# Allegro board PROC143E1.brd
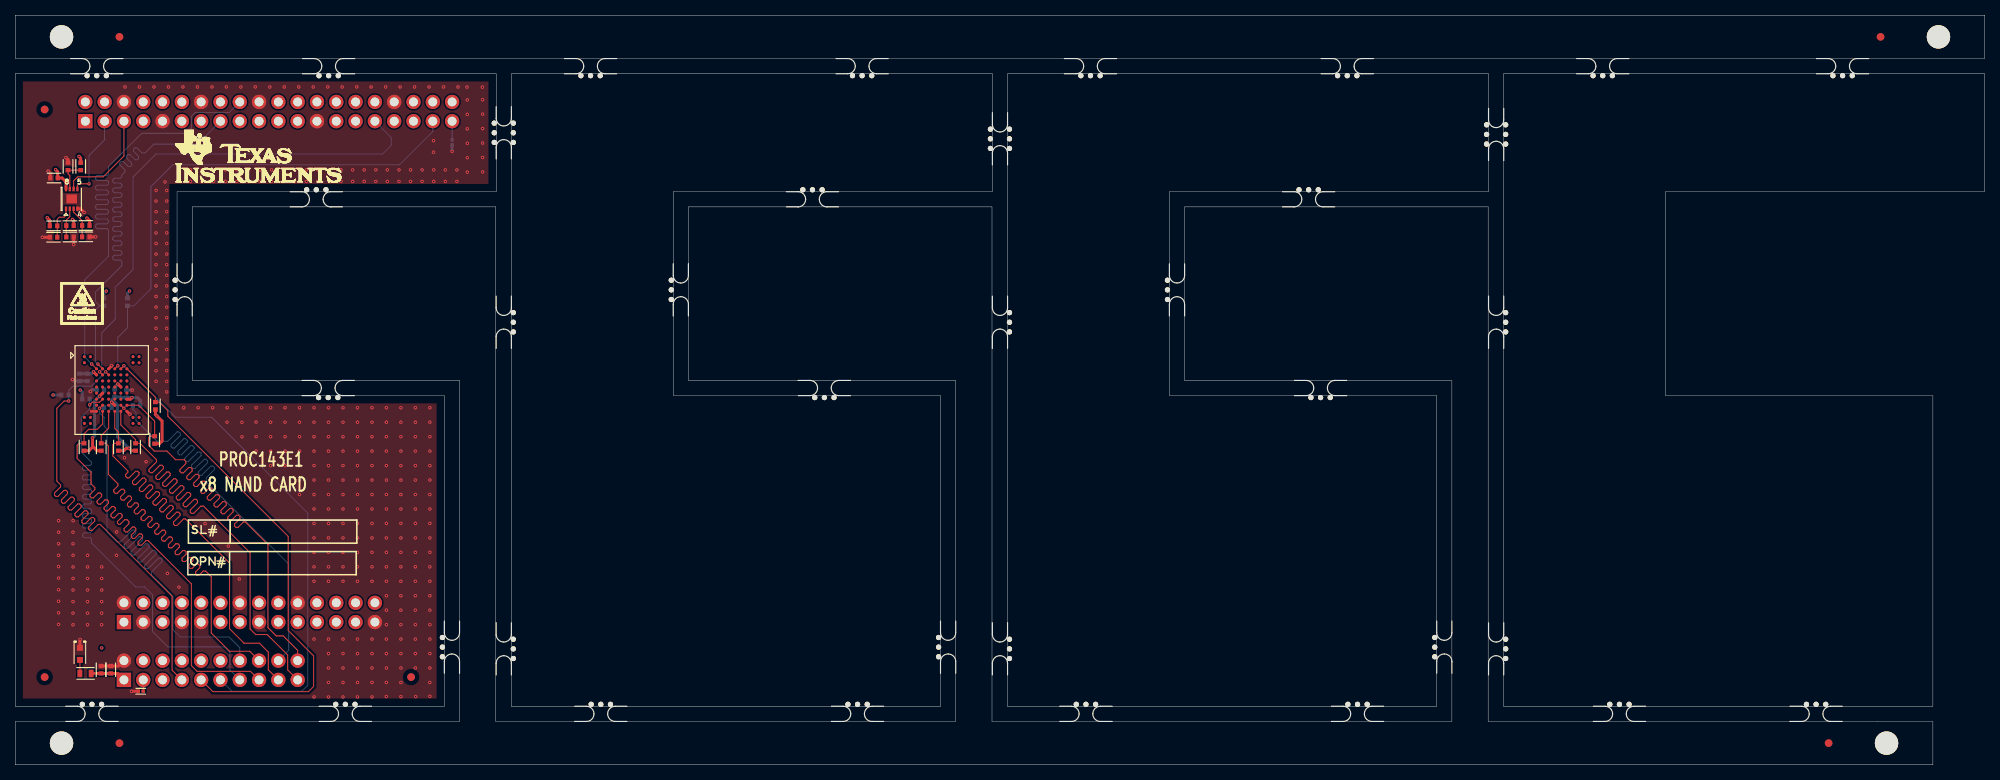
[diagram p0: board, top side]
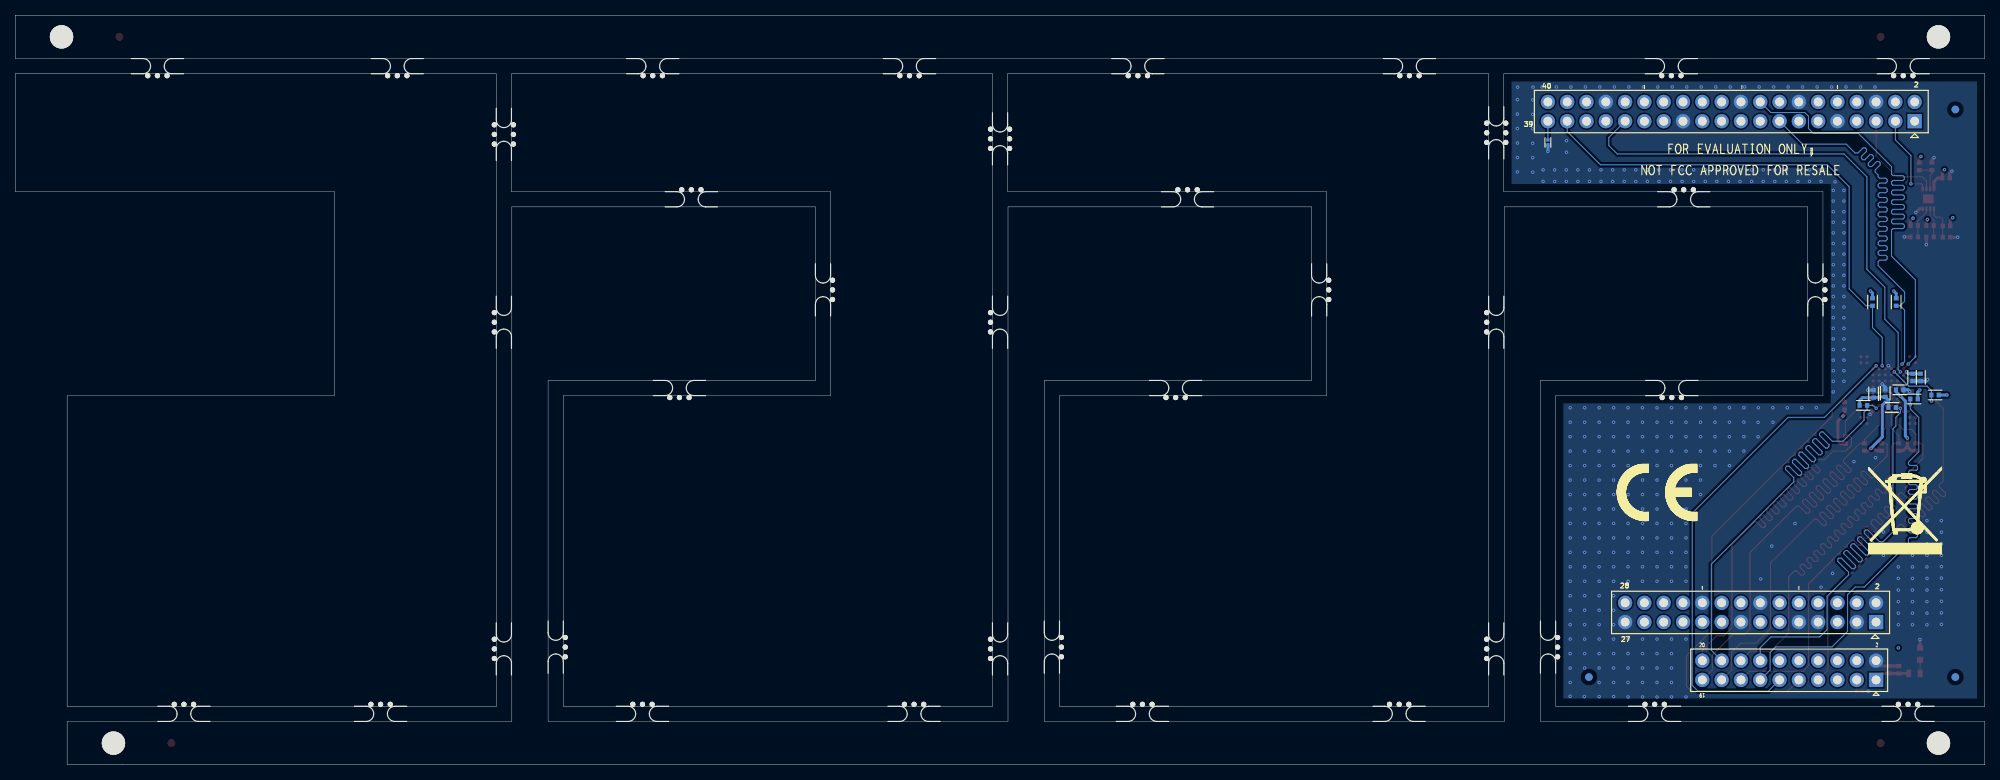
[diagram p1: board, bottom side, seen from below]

Outline 259.15 x 98.76 mm; copper layers: TOP, L02_GND01, L03_PWR01, BOTTOM. Coordinates in mm from the lower left corner of the outline.
Outline path: 0,98.76 0,93.05 259.15,93.05 259.15,98.76 0,98.76 ; 0,91.05 0,7.71 56.46,7.71 56.46,48.64 21.29,48.64 21.29,75.51 63.29,75.51 63.29,91.05 0,91.05 ; 0,5.71 0,0 252.32,0 252.32,5.71 193.81,5.71 193.81,73.51 153.87,73.51 153.87,50.64 189.04,50.64 189.04,5.71 128.52,5.71 128.52,73.51 88.58,73.51 88.58,50.64 123.75,50.64 123.75,5.71 63.24,5.71 63.24,73.51 23.29,73.51 23.29,50.64 58.46,50.64 58.46,5.71 0,5.71 ; 65.29,91.05 65.29,7.72 65.29,7.71 121.75,7.71 121.75,48.64 86.58,48.64 86.58,75.51 128.57,75.51 128.57,91.05 65.29,91.05 ; 130.57,91.05 130.57,7.72 130.57,7.71 187.04,7.71 187.04,48.64 151.87,48.64 151.87,75.51 193.86,75.51 193.86,91.05 130.57,91.05 ; 195.86,91.05 195.86,7.72 195.86,7.71 252.32,7.71 252.32,48.64 217.15,48.64 217.15,75.51 259.14,75.51 259.14,91.05 195.86,91.05

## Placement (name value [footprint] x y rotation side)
C1  0.1uF  [CAP0402_0-75]  5.1 77.31 180 top
C2  2.2uF  [CAP0402_0-75]  11.3 12.53 90 top
C3  0.1uF  [CAP0402_0-75]  12.57 12.53 270 top
C4  0.1uF  [CAP0402_0-75]  9.49 51.04 270 bottom
C5  2.2uF  [CAP0402_0-75]  8.47 51.04 270 bottom
C6  0.1uF  [CAP0402_0-75]  11.2 49.41 180 bottom
C7  0.1uF  [CAP0402_0-75]  13.1 48.96 90 bottom
C8  0.1uF  [CAP0402_0-75]  14.63 48.87 90 bottom
J1  RECP_2X20  [RECPT_2X20_CRD-081413-A-20_S_T_8-6]  9.23 84.79 0 bottom
J2  RECP_2X14  [RECPT_2X14_CRD-081413-A-14_S_T_8-6]  14.31 18.81 0 bottom
J3  RECP_2X10  [RECPT_2X10_CRD-081413-A_S_T_8-6]  14.31 11.19 0 bottom
LD1  150060VS75000  [LED_150060SS75000_70X40_SMD_0-8]  8.51 14.62 270 top
NOREF  -  [unnamed]  64.29 83.27 90 top
NOREF#2  -  [#2]  -399.03 -80.96 0 top
NOREF#3  -  [unnamed#3]  41.19 49.64 180 top
NOREF#4  -  [#2]  -31.1 -80.63 0 top
NOREF#5  -  [unnamed#4]  52.09 11.56 90 top
NOREF#6  -  [unnamed#3]  152.87 62.57 90 top
NOREF#7  -  [unnamed#3]  129.57 58.3 270 top
NOREF#8  -  [#2]  0 98.76 0 top
NOREF#9  -  [#2]  0 91.05 0 top
NOREF#10  -  [unnamed#3]  22.29 62.57 90 top
NOREF#11  -  [#2]  -76.48 -79.92 0 top
NOREF#12  -  [unnamed#3]  240.44 92.05 180 top
NOREF#13  -  [unnamed#4]  238.61 2.86 0 top
NOREF#14  -  [unnamed#4]  245.44 95.9 0 top
NOREF#15  -  [unnamed#3]  140.89 6.71 0 top
NOREF#16  -  [#2]  56.46 48.64 90 top
NOREF#17  -  [unnamed#4]  6.1 2.86 0 top
NOREF#18  -  [unnamed#3]  110.84 6.71 0 top
NOREF#19  -  [#2]  56.46 7.71 90 top
NOREF#20  -  [unnamed#3]  106.47 49.64 180 top
NOREF#21  -  [unnamed#3]  208.88 92.05 180 top
NOREF#22  -  [unnamed#4]  3.88 11.56 90 top
NOREF#23  -  [unnamed#4]  3.88 86.34 90 top
NOREF#24  -  [unnamed]  129.57 82.47 90 top
NOREF#25  -  [unnamed#4]  253.06 95.9 0 top
NOREF#26  -  [unnamed#4]  6.1 95.9 0 top
NOREF#27  -  [unnamed#3]  194.86 15.28 270 top
NOREF#28  -  [unnamed#4]  246.23 2.86 0 top
NOREF#29  -  [#2]  56.46 7.71 90 top
NOREF#30  -  [unnamed]  194.86 83.05 90 top
NOREF#31  -  [unnamed#3]  75.7 92.05 180 top
NOREF#32  -  [#2]  -406.51 198 0 top
NOREF#33  -  [unnamed#3]  111.43 92.05 180 top
NOREF#34  -  [unnamed#3]  175.27 92.05 180 top
NOREF#35  -  [#2]  0 0 90 top
NOREF#36  -  [unnamed#4]  13.72 95.9 0 top
NOREF#37  -  [unnamed#3]  176.62 6.71 0 top
NOREF#38  -  [unnamed#3]  41.24 92.05 180 top
NOREF#39  -  [unnamed#3]  104.9 74.51 0 top
NOREF#40  -  [unnamed#3]  10.73 92.05 180 top
NOREF#41  -  [#2]  63.29 75.51 90 top
NOREF#42  -  [unnamed#3]  10.1 6.71 0 top
NOREF#43  -  [unnamed#4]  13.72 2.86 0 top
NOREF#44  -  [unnamed#3]  129.57 15.28 270 top
NOREF#45  -  [unnamed#3]  141.49 92.05 180 top
NOREF#46  -  [unnamed#3]  39.62 74.51 0 top
NOREF#47  -  [unnamed#3]  64.29 15.28 270 top
NOREF#48  -  [unnamed#3]  170.19 74.51 0 top
NOREF#49  -  [unnamed#3]  236.96 6.71 0 top
NOREF#50  -  [unnamed#3]  57.46 15.5 90 top
NOREF#51  -  [unnamed#3]  188.04 15.5 90 top
NOREF#52  -  [#2]  267.28 -44.9 0 top
NOREF#53  -  [unnamed#3]  194.86 58.3 270 top
NOREF#54  -  [unnamed#3]  122.75 15.5 90 top
NOREF#55  -  [unnamed#3]  87.58 62.57 90 top
NOREF#56  -  [unnamed#3]  64.29 58.3 270 top
NOREF#57  -  [unnamed#3]  43.44 6.71 0 top
NOREF#58  -  [unnamed#3]  171.76 49.64 180 top
NOREF#59  -  [unnamed#3]  211.08 6.71 0 top
NOREF#60  -  [unnamed#3]  77.05 6.71 0 top
NOREF#61  -  [unnamed#4]  3.88 11.56 270 bottom
NOREF#62  -  [unnamed#4]  52.09 11.56 270 bottom
NOREF#63  -  [unnamed#4]  3.88 86.34 270 bottom
R1  10K  [RES0402_0-5]  6.95 78.83 90 top
R2  10K  [RES0402_0-5]  8.62 78.83 270 top
R3  10K  [RES0402_0-5]  9.3 71.05 180 top
R4  10K  [RES0402_0-5]  7.21 71.03 180 top
R5  10K  [RES0402_0-5]  5.04 71 0 top
R6  10K  [RES0402_0-5]  9.3 69.55 0 top
R7  10K  [RES0402_0-5]  7.21 69.54 0 top
R8  10K  [RES0402_0-5]  5.04 69.5 180 top
R9  10K  [RES0402_0-5]  18.44 47.3 90 top
R10  10K  [RES0402_0-5]  18.35 42.8 90 top
R11  10K  [RES0402_0-5]  9.06 41.87 90 top
R12  10K  [RES0402_0-5]  11.32 41.87 90 top
R13  10K  [RES0402_0-5]  13.58 41.87 90 top
R14  10K  [RES0402_0-5]  15.84 41.87 90 top
R15  160E  [RES0603_0-75]  9.25 12.04 180 top
R16  0E  [RES0201_0-5]  16.52 9.7 0 top
R17  0E  [RES0201_0-5]  57.49 82 90 bottom
R18  10K  [RES0402_0-5]  11.66 60.97 270 bottom
R19  10K  [RES0402_0-5]  14.77 60.97 270 bottom
R20  10K  [RES0402_0-5]  6.55 48.72 0 bottom
R21  10K  [RES0402_0-5]  12.19 47.08 180 bottom
R22  10K  [RES0402_0-5]  9.31 48.19 0 bottom
R23  10K  [RES0402_0-5]  15.98 47.35 180 bottom
U1  M24512-DFMC6TG  [UFDFPN8_M24512_120X80_0-6]  7.44 74.56 90 top
U2  MT29F8G08ADAFAH4-AAT  [FBGA63_31-49_360X440_1]  12.7 49.37 0 top

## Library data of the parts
C1-C8 = CAP
J1 = RECP_20X2
J2 = RECP_14X2
J3 = RECP_10X2
LD1 = DIODE_LED
R1-R23 = RESISTOR
U1 = M24512_UFDFPN8
U2 = MT29F8G08ADAFAH4_VFBAG63

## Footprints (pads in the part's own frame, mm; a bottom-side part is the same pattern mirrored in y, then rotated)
CAP0402_0-75
  rect 0.559x0.635 smd: 1(-0.49,0) 2(0.49,0)
FBGA63_31-49_360X440_1
  round 0.406 smd: A1(-3.6,4.4) A2(-2.8,4.4) A9(2.8,4.4) A10(3.6,4.4) B1(-3.6,3.6) B9(2.8,3.6) B10(3.6,3.6) C3(-2,2.8) C4(-1.2,2.8) C5(-0.4,2.8) C6(0.4,2.8) C7(1.2,2.8) C8(2,2.8) D3(-2,2) D4(-1.2,2) D5(-0.4,2) D6(0.4,2) D7(1.2,2) D8(2,2) E3(-2,1.2) E4(-1.2,1.2) E5(-0.4,1.2) E6(0.4,1.2) E7(1.2,1.2) E8(2,1.2) F3(-2,0.4) F4(-1.2,0.4) F5(-0.4,0.4) F6(0.4,0.4) F7(1.2,0.4) F8(2,0.4) G3(-2,-0.4) G4(-1.2,-0.4) G5(-0.4,-0.4) G6(0.4,-0.4) G7(1.2,-0.4) G8(2,-0.4) H3(-2,-1.2) H4(-1.2,-1.2) H5(-0.4,-1.2) H6(0.4,-1.2) H7(1.2,-1.2) H8(2,-1.2) J3(-2,-2) J4(-1.2,-2) J5(-0.4,-2) J6(0.4,-2) J7(1.2,-2) J8(2,-2) K3(-2,-2.8) K4(-1.2,-2.8) K5(-0.4,-2.8) K6(0.4,-2.8) K7(1.2,-2.8) K8(2,-2.8) L1(-3.6,-3.6) L2(-2.8,-3.6) L9(2.8,-3.6) L10(3.6,-3.6) M1(-3.6,-4.4) M2(-2.8,-4.4) M9(2.8,-4.4) M10(3.6,-4.4)
LED_150060SS75000_70X40_SMD_0-8
  rect 0.787x0.787 smd: 1(-0.8,0) 2(0.8,0)
RECPT_2X10_CRD-081413-A_S_T_8-6
  rect 1.88x1.88 hole 1.168: 1(0,0)
  round 1.88 hole 1.168: 2(0,-2.54) 3(2.54,0) 4(2.54,-2.54) 5(5.08,0) 6(5.08,-2.54) 7(7.62,0) 8(7.62,-2.54) 9(10.16,0) 10(10.16,-2.54) 11(12.7,0) 12(12.7,-2.54) 13(15.24,0) 14(15.24,-2.54) 15(17.78,0) 16(17.78,-2.54) 17(20.32,0) 18(20.32,-2.54) 19(22.86,0) 20(22.86,-2.54)
RECPT_2X14_CRD-081413-A-14_S_T_8-6
  rect 1.88x1.88 hole 1.168: 1(0,0)
  round 1.88 hole 1.168: 2(0,-2.54) 3(2.54,0) 4(2.54,-2.54) 5(5.08,0) 6(5.08,-2.54) 7(7.62,0) 8(7.62,-2.54) 9(10.16,0) 10(10.16,-2.54) 11(12.7,0) 12(12.7,-2.54) 13(15.24,0) 14(15.24,-2.54) 15(17.78,0) 16(17.78,-2.54) 17(20.32,0) 18(20.32,-2.54) 19(22.86,0) 20(22.86,-2.54) 21(25.4,0) 22(25.4,-2.54) 23(27.94,0) 24(27.94,-2.54) 25(30.48,0) 26(30.48,-2.54) 27(33.02,0) 28(33.02,-2.54)
RECPT_2X20_CRD-081413-A-20_S_T_8-6
  rect 1.88x1.88 hole 1.168: 1(0,0)
  round 1.88 hole 1.168: 2(0,-2.54) 3(2.54,0) 4(2.54,-2.54) 5(5.08,0) 6(5.08,-2.54) 7(7.62,0) 8(7.62,-2.54) 9(10.16,0) 10(10.16,-2.54) 11(12.7,0) 12(12.7,-2.54) 13(15.24,0) 14(15.24,-2.54) 15(17.78,0) 16(17.78,-2.54) 17(20.32,0) 18(20.32,-2.54) 19(22.86,0) 20(22.86,-2.54) 21(25.4,0) 22(25.4,-2.54) 23(27.94,0) 24(27.94,-2.54) 25(30.48,0) 26(30.48,-2.54) 27(33.02,0) 28(33.02,-2.54) 29(35.56,0) 30(35.56,-2.54) 31(38.1,0) 32(38.1,-2.54) 33(40.64,0) 34(40.64,-2.54) 35(43.18,0) 36(43.18,-2.54) 37(45.72,0) 38(45.72,-2.54) 39(48.26,0) 40(48.26,-2.54)
RES0201_0-5
  rect 0.457x0.432 smd: 1(-0.33,0) 2(0.33,0)
RES0402_0-5
  rect 0.559x0.635 smd: 1(-0.49,0) 2(0.49,0)
RES0603_0-75
  rect 0.635x0.991 smd: 1(-0.74,0) 2(0.74,0)
UFDFPN8_M24512_120X80_0-6
  rect 0.61x0.305 smd: 1(-1.3,0.75) 2(-1.3,0.25) 3(-1.3,-0.25) 4(-1.3,-0.75) 5(1.3,-0.75) 6(1.3,-0.25) 7(1.3,0.25) 8(1.3,0.75)
  rect 1.194x1.397 smd: 9(0,0)
unnamed
  round 0.686 hole 0.813 unplated: (-1.27,1.254) (-1.27,-1.254) (0,1.254) (0,-1.254) (1.27,1.254) (1.27,-1.254)
unnamed#3
  round 0.686 hole 0.813 unplated: (-1.27,1.254) (0,1.254) (1.27,1.254)
unnamed#4
  round 1.016 smd: (0,0)

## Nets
DGND: C1.2 C2.2 C3.1 C4.2 C5.2 C6.2 C7.2 C8.2 J1.6 J1.9 J1.14 J1.20 J1.25 J1.34 J2.2 J2.3 J2.7 J2.9 J2.14 J2.15 J2.20 J2.27 J3.2 LD1.1(CATHODE) R1.2 R6.2 R7.2 R8.2 R16.1 R17.1 U1.4(VSS) U1.9(EP) U2.C5(VSS#C5) U2.F7(VSS#F7) U2.K3(VSS#K3) U2.K8(VSS#K8)
VCC_3V3_NAND: C1.1 C2.1 C3.2 C4.1 C5.1 C6.1 C7.1 C8.1 J3.1 R2.1 R3.1 R4.1 R5.1 R9.1 R10.1 R11.1 R12.1 R13.1 R14.1 R15.1 R18.1 R19.1 R20.1 R21.1 R22.1 R23.1 U1.8(VCC) U2.D3(VCC#D3) U2.G4(VCC#G4) U2.H8(VCC#H8) U2.J6(VCC#J6)
VCC_3V3_SYS: J2.1
EEPROM1_A0_SC: R5.2 R8.1 U1.1(E0)
EEPROM1_A1_SC: R4.2 R7.1 U1.2(E1)
EEPROM1_A2_SC: R3.2 R6.1 U1.3(E2)
EEPROM1_WP_SC: R1.1 R2.2 U1.7(W\C\)
EXP_GPIO0_32: J1.15 R18.2 U2.C4(ALE)
EXP_GPIO0_33: J1.31 U2.D4(RE#)
EXP_GPIO0_39: J1.18 U2.C3(WP#)
EXP_GPIO0_41: J1.37 R19.2 U2.C6(CE#)
GPIO0_43/I2C2_SCL: J1.5 U1.6(SCL)
GPIO0_44/I2C2_SDA: J1.3 U1.5(SDA)
PR0_PRU0_GPO0: J3.13 R22.2 U2.H4(I/O0)
PR0_PRU0_GPO1: J3.14 R21.2 U2.J4(I/O1)
PR0_PRU0_GPO2: J3.15 R11.2 U2.K4(I/O2)
PR0_PRU0_GPO3: J3.16 R12.2 U2.K5(I/O3)
PR0_PRU0_GPO4: J3.17 R13.2 U2.K6(I/O4)
PR0_PRU0_GPO5: J3.18 R23.2 U2.J7(I/O5)
PR0_PRU0_GPO6: J3.19 R14.2 U2.K7(I/O6)
PR0_PRU0_GPO7: J3.20 R10.2 U2.J8(I/O7)
PR0_PRU0_GPO11: J3.7 R20.2 U2.D5(CLE)
PR0_PRU0_GPO12: J3.9 R9.2 U2.C8(R/B#)
PR0_PRU0_GPO14: J3.11 U2.C7(WE#)
PRU_DETECT: J3.3 R16.2
RPI_HAT_DETECT: J1.39 R17.2
N19755073: LD1.2(ANODE) R15.2

Pads without a net: J1 1 2 4 7 8 10 11 12 13 16 17 19 21 22 23 24 26 27 28 29 30 32 33 35 36 38 40; J2 4 5 6 8 10 11 12 13 16 17 18 19 21 22 23 24 25 26 28; J3 4 5 6 8 10 12; U2 A1 A2 A9 A10 B1 B9 B10 D6 D7 D8 E3 E4 E5 E6 E7 E8 F3 F4 F5 F6 F8 G3 G5 G6 G7 G8 H3 H5 H6 H7 J3 J5 L1 L2 L9 L10 M1 M2 M9 M10

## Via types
v1: diameter 0.457, hole 0.203, TOP to BOTTOM, 414 vias

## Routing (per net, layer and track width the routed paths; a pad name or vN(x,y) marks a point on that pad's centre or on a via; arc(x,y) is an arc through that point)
DGND: length 18.8
  TOP w0.305: 10,46.57 10.01,46.57 U2.K3
  TOP w0.381: U1.4 8.58,73.26 v1(9.07,72.77) ; R1.2 6.95,79.72 v1(6.68,80) ; C2.2 C3.1 13.6,13.02 J3.2 ; U2.K8 v1(15.1,46.17) ; LD1.1 8.51,16.49 v1(8.53,16.51) ; v1(4.33,78.21) 4.61,77.93 C1.2 ; U2.F7 v1(13.5,50.17) ; U2.C5 v1(12.7,52.57) ; R16.1 v1(15.3,9.7) ; R6.2 v1(10.58,69.55) ; R7.2 v1(7.7,68.53) ; R8.2 v1(3.57,69.5)
  BOTTOM w0.381: R17.1 v1(57.49,80.81) ; v1(9.87,49.18) 10.11,49.41 C6.2 ; C7.2 13.1,49.77 v1(13.5,50.17) ; C8.2 v1(15.4,49.36) ; v1(7.52,50.76) 7.73,50.55 C5.2 C4.2
  vias: v1(5.71,32.17) v1(5.71,30.65) v1(5.71,29.12) v1(5.71,27.6) v1(5.71,26.12) v1(5.71,24.59) v1(5.71,23.07) v1(5.71,21.55) v1(5.71,20.02) v1(5.71,18.5) v1(7.61,32.17) v1(7.61,30.65) v1(7.61,29.12) v1(7.61,27.6) v1(7.61,26.07) v1(7.61,24.55) v1(7.61,23.03) v1(7.61,21.5) v1(7.61,19.98) v1(7.61,18.45) v1(9.52,27.6) v1(9.52,26.07) v1(9.52,24.55) v1(9.52,23.03) v1(9.52,21.5) v1(9.52,19.98) v1(9.52,18.45) v1(11.38,26.08) v1(11.38,24.55) v1(11.38,23.03) v1(11.38,21.5) v1(11.38,19.98) v1(11.38,18.46) v1(13.34,30.68) v1(13.33,27.6) v1(14.38,40.46) v1(14.45,89.31) v1(16.35,89.31) v1(17.22,39.94) v1(18.26,89.31) v1(18.54,75.67) v1(18.54,74.27) v1(18.54,72.88) v1(18.54,71.48) v1(18.54,70.08) v1(18.54,68.68) v1(18.54,67.29) v1(18.54,65.89) v1(18.54,64.49) v1(18.54,63.1) v1(18.54,61.7) v1(18.54,60.3) v1(18.54,58.91) v1(18.54,57.51) v1(18.54,56.11) v1(18.54,54.71) v1(18.54,53.32) v1(18.54,51.92) v1(18.54,50.52) v1(19.71,76.8) v1(19.94,75.67) v1(19.94,74.27) v1(19.94,72.88) v1(19.94,71.48) v1(19.94,70.08) v1(19.94,68.68) v1(19.94,67.29) v1(19.94,65.89) v1(19.94,64.49) v1(19.94,63.1) v1(19.94,61.7) v1(19.94,60.3) v1(19.94,58.91) v1(19.94,57.51) v1(19.94,56.11) v1(19.94,54.71) v1(19.94,53.32) v1(19.94,51.92) v1(19.94,50.52) v1(19.94,49.13) v1(20.03,25.22) v1(20.16,89.31) v1(21.54,78.38) v1(21.54,76.86) v1(21.54,23.4) v1(22.07,89.31) v1(22.17,47.04) v1(23.06,78.38) v1(23.06,76.86) v1(23.97,89.31) v1(24.08,47.04) v1(24.59,78.38) v1(24.59,76.86) v1(24.98,31.79) v1(25.88,89.31) v1(25.98,47.04) v1(26.11,78.38) v1(26.11,76.86) v1(27.64,78.38) v1(27.64,76.86) v1(27.78,89.31) v1(27.89,47.04) v1(27.87,45.13) v1(28.04,28.82) v1(29.16,78.38) v1(29.16,76.86) v1(29.49,24.48) v1(29.69,89.31) v1(29.79,47.04) v1(29.84,45.12) v1(29.84,43.21) v1(30.68,78.38) v1(30.68,76.86) v1(31.59,89.31) v1(31.7,47.04) v1(31.7,45.15) v1(31.7,43.24) v1(31.7,41.34) v1(32.21,78.38) v1(32.21,76.86) v1(33.5,89.31) v1(33.6,47.04) v1(33.6,45.14) v1(33.6,43.23) v1(33.6,41.33) v1(33.6,39.42) v1(33.73,78.38) v1(33.73,76.86) v1(35.26,78.38) v1(35.26,76.86) v1(35.4,89.31) v1(35.51,47.04) v1(35.51,45.14) v1(35.51,43.23) v1(35.51,41.33) v1(35.51,39.42) v1(36.78,78.38) v1(36.78,76.86) v1(37.31,89.31) v1(37.41,47.04) v1(37.41,45.14) v1(37.41,43.23) v1(37.41,41.33) v1(37.41,39.42) v1(37.41,37.52) v1(37.41,35.61) v1(38.3,78.38) v1(38.3,76.86) v1(39.21,89.31) v1(39.32,47.04) v1(39.32,45.14) v1(39.32,43.23) v1(39.32,41.33) v1(39.32,39.42) v1(39.32,37.52) v1(39.32,35.61) v1(39.32,33.71) v1(39.32,31.8) v1(39.32,29.9) v1(39.32,27.99) v1(39.32,26.09) v1(39.32,24.18) v1(39.32,16.56) v1(39.32,8.94) v1(39.83,78.38) v1(39.83,76.86) v1(41.12,89.31) v1(41.22,47.04) v1(41.22,45.14) v1(41.22,43.23) v1(41.22,41.33) v1(41.22,39.42) v1(41.22,37.52) v1(41.22,35.61) v1(41.22,33.71) v1(41.22,31.8) v1(41.22,29.9) v1(41.22,27.99) v1(41.22,26.09) v1(41.22,24.18) v1(41.22,16.56) v1(41.22,14.66) v1(41.22,12.75) v1(41.22,10.85) v1(41.22,8.94) v1(41.35,78.38) v1(41.35,76.86) v1(42.88,78.38) v1(42.88,76.86) v1(43.02,89.31) v1(43.13,47.04) v1(43.13,45.14) v1(43.13,43.23) v1(43.13,41.33) v1(43.13,39.42) v1(43.13,37.52) v1(43.13,35.61) v1(43.13,33.71) v1(43.13,31.8) v1(43.13,29.9) v1(43.13,27.99) v1(43.13,26.09) v1(43.13,24.18) v1(43.13,16.56) v1(43.13,14.66) v1(43.13,12.75) v1(43.13,10.85) v1(43.13,8.94) v1(44.4,78.38) v1(44.4,76.86) v1(44.93,89.31) v1(45.03,47.04) v1(45.03,45.14) v1(45.03,43.23) v1(45.03,41.33) v1(45.03,39.42) v1(45.03,37.52) v1(45.03,35.61) v1(45.03,33.71) v1(45.03,31.8) v1(45.03,29.9) v1(45.03,27.99) v1(45.03,26.09) v1(45.03,24.18) v1(45.03,16.56) v1(45.03,14.66) v1(45.03,12.75) v1(45.03,10.85) v1(45.03,8.94) v1(45.92,78.38) v1(45.92,76.86) v1(46.83,89.31) v1(46.94,47.04) v1(46.94,45.14) v1(46.94,43.23) v1(46.94,41.33) v1(46.94,39.42) v1(46.94,37.52) v1(46.94,35.61) v1(46.94,33.71) v1(46.94,31.8) v1(46.94,29.9) v1(46.94,27.99) v1(46.94,26.09) v1(46.94,24.18) v1(46.94,16.56) v1(46.94,14.66) v1(46.94,12.75) v1(46.94,10.85) v1(46.94,8.94) v1(47.45,78.38) v1(47.45,76.86) v1(48.74,89.31) v1(48.84,47.04) v1(48.84,45.14) v1(48.84,43.23) v1(48.84,41.33) v1(48.84,39.42) v1(48.84,37.52) v1(48.84,35.61) v1(48.84,33.71) v1(48.84,31.8) v1(48.84,29.9) v1(48.84,27.99) v1(48.84,26.09) v1(48.84,24.18) v1(48.84,22.28) v1(48.84,20.37) v1(48.84,18.47) v1(48.84,16.56) v1(48.84,14.66) v1(48.84,12.75) v1(48.84,10.85) v1(48.82,8.99) v1(48.97,78.38) v1(48.97,76.86) v1(50.5,78.38) v1(50.5,76.86) v1(50.64,89.31) v1(50.75,47.04) v1(50.75,45.14) v1(50.75,43.23) v1(50.75,41.33) v1(50.75,39.42) v1(50.75,37.52) v1(50.75,35.61) v1(50.75,33.71) v1(50.75,31.8) v1(50.75,29.9) v1(50.75,27.99) v1(50.75,26.09) v1(50.75,24.18) v1(50.75,22.28) v1(50.75,20.37) v1(50.75,18.47) v1(50.75,16.56) v1(50.75,14.66) v1(50.75,12.75) v1(50.75,10.85) v1(50.75,8.98) v1(52.02,78.38) v1(52.02,76.86) v1(52.55,89.31) v1(52.65,47.04) v1(52.65,45.14) v1(52.65,43.23) v1(52.65,41.33) v1(52.65,39.42) v1(52.65,37.52) v1(52.65,35.61) v1(52.65,33.71) v1(52.65,31.8) v1(52.65,29.9) v1(52.65,27.99) v1(52.65,26.09) v1(52.65,24.18) v1(52.65,22.28) v1(52.65,20.37) v1(52.65,18.47) v1(52.65,16.56) v1(52.65,14.66) v1(52.65,12.75) v1(52.69,8.99) v1(53.54,78.38) v1(53.54,76.86) v1(54.45,89.31) v1(54.56,47.04) v1(54.56,45.14) v1(54.56,43.23) v1(54.56,41.33) v1(54.56,39.42) v1(54.56,37.52) v1(54.56,35.61) v1(54.56,33.71) v1(54.56,31.8) v1(54.56,29.9) v1(54.56,27.99) v1(54.56,26.09) v1(54.56,24.18) v1(54.56,22.28) v1(54.56,20.37) v1(54.56,18.47) v1(54.56,16.56) v1(54.56,14.66) v1(54.56,12.75) v1(54.56,10.85) v1(54.56,9.02) v1(55.04,82.23) v1(55.04,80.71) v1(55.07,78.38) v1(55.07,76.86) v1(56.36,89.31) v1(56.59,78.38) v1(56.59,76.86) v1(58.12,78.38) v1(58.12,76.86) v1(58.26,89.31) v1(59.44,89.28) v1(59.49,87.6) v1(59.49,85.69) v1(59.49,83.79) v1(59.49,81.88) v1(59.49,79.98) v1(59.49,78.07) v1(61.47,89.28) v1(61.5,87.63) v1(61.5,85.73) v1(61.5,83.82) v1(61.5,81.92) v1(61.5,80.01) v1(61.5,78.11)
VCC_3V3_NAND: length 65.8
  TOP w0.381: v1(5.31,78.41) 5.59,78.13 C1.1 6.19,77.31 6.69,76.81 U1.8 ; R4.1 7.7,71.69 v1(7.54,71.85) ; R2.1 8.62,79.93 v1(8.4,80.14) ; v1(15.35,48.37) 15.16,48.17 U2.H8 ; v1(4.22,72.08) 4.55,71.74 R5.1 ; J3.1 13.45,12.04 C3.2 C2.1 R15.1 ; U2.D3 v1(10.3,51.77) ; U2.J6 v1(12.7,47.77) ; 10.18,41.98 v1(10.18,43.06) ; 10.18,41.98 10.18,41.85 9.71,41.38 R11.1 ; 10.18,41.98 10.77,41.38 R12.1 ; v1(9.44,72.02) 9.79,71.67 R3.1 ; U2.G4 v1(11.1,48.57) ; R10.1 18.99,42.31 19.32,42.65 19.32,45.28 v1(18.65,45.95) 18.44,46.16 R9.1 ; R14.1 15.29,41.38 v1(14.98,41.7) 14.61,41.7 14.29,41.38 R13.1
  L02_GND01 w0.762: v1(11.98,62.4) 14.31,62.4 14.32,62.41 v1(15.04,62.41)
  L03_PWR01 w0.381: v1(11.1,48.57) 11.63,48.57 11.84,48.37 v1(15.35,48.37) 15.93,48.37 15.94,48.38 17.74,48.38 18.65,47.46 v1(18.65,45.95)
  BOTTOM w0.381: R20.1 v1(4.98,48.72) ; C5.1 C4.1 10.06,51.53 v1(10.3,51.77) ; R19.1 14.77,62.14 v1(15.04,62.41) ; R18.1 11.66,62.09 v1(11.98,62.4) ; v1(12.7,47.77) 12.7,48.07 C7.1 13.91,48.47 14,48.38 C8.1 14.65,48.37 v1(15.35,48.37) 16.1,48.37 16.4,48.07 16.4,48.06 16.47,47.99 R23.1 ; v1(12.7,47.77) 13.1,47.77 13.48,47.39 13.48,43.2 v1(14.98,41.7) ; v1(12.7,47.77) 12.68,47.75 R21.1 ; v1(10.18,43.06) 10.46,43.33 10.46,47.93 v1(11.1,48.57) 11.69,49.17 C6.1 ; R22.1 8.82,49.1 v1(8.55,49.37)
  vias: v1(11.38,15.41)
EEPROM1_A0_SC: length 4.6
  TOP w0.127: R8.1 R5.2 5.53,71.87 5.81,72.15 6.43,72.15 6.69,72.4 U1.1
EEPROM1_A1_SC: length 3.9
  TOP w0.127: U1.2 7.19,72.22 6.72,71.76 R4.2 R7.1
EEPROM1_A2_SC: length 4.2
  TOP w0.127: R6.1 R3.2 8.81,71.69 7.69,72.81 U1.3
EEPROM1_WP_SC: length 4.2
  TOP w0.127: R2.2 R1.1 6.95,77.87 7.19,77.64 U1.7
EXP_GPIO0_32: length 68.5
  TOP w0.127: U2.C4 v1(10.89,52.79)
  BOTTOM w0.127: 11.14,60.48 11.13,60.48 10.55,59.9 10.55,53.12 v1(10.89,52.79) ; 11.14,60.48 R18.2 ; 11.14,60.48 10.55,61.06 10.55,62.29 14.03,65.77 14.03,66.3 13.85,66.48 13.02,66.48 12.84,66.67 12.84,66.93 13.02,67.12 13.85,67.12 14.03,67.31 14.03,67.57 13.85,67.75 13.02,67.75 12.84,67.94 12.84,68.2 13.02,68.39 13.85,68.39 14.03,68.58 14.03,68.84 13.85,69.02 13.02,69.02 12.84,69.21 12.84,69.47 13.02,69.66 13.85,69.66 14.03,69.85 14.03,70.11 13.85,70.29 13.02,70.29 12.84,70.48 12.84,70.74 13.02,70.93 13.85,70.93 14.03,71.12 14.03,71.38 13.85,71.56 13.02,71.56 12.84,71.75 12.84,72.01 13.02,72.2 13.85,72.2 14.03,72.39 14.03,72.65 13.85,72.83 13.02,72.83 12.84,73.02 12.84,73.28 13.02,73.47 13.85,73.47 14.03,73.66 14.03,73.92 13.85,74.1 13.02,74.1 12.84,74.29 12.84,74.55 13.02,74.74 13.85,74.74 14.03,74.93 14.03,75.19 13.85,75.37 13.02,75.37 12.84,75.56 12.84,75.82 13.02,76.01 13.85,76.01 14.03,76.2 14.03,76.46 13.85,76.64 13.02,76.64 12.84,76.83 12.84,77.09 13.02,77.28 13.85,77.28 14.03,77.47 14.03,77.7 14.43,78.1 14.43,78.36 13.76,79.04 13.76,79.3 13.95,79.48 14.21,79.48 14.88,78.81 15.15,78.81 15.33,79 15.33,79.26 14.66,79.93 14.66,80.2 14.85,80.38 15.11,80.38 15.78,79.71 16.04,79.71 16.23,79.9 16.23,80.16 15.56,80.83 15.56,81.09 15.75,81.28 16.01,81.28 16.68,80.61 17.07,80.61 18.23,81.77 23.98,81.77 J1.15
EXP_GPIO0_33: length 67.8
  TOP w0.127: U2.D4 v1(11.1,51.77)
  BOTTOM w0.127: v1(11.1,51.77) 11.4,52.07 11.4,56.95 13.15,58.7 13.15,62.92 15.51,65.28 15.51,77.46 18.52,80.48 48.36,80.48 49.47,81.59 49.47,82.65 J1.31
EXP_GPIO0_39: length 68
  TOP w0.127: U2.C3 v1(10.06,52.81)
  BOTTOM w0.127: J1.18 28.14,85.93 23.69,85.93 23.2,85.45 23.2,83.84 22.56,83.19 16.64,83.19 12.27,78.82 12.27,77.81 12.08,77.62 10.77,77.62 10.58,77.44 10.58,77.17 10.77,76.99 12.08,76.99 12.27,76.8 12.27,76.54 12.08,76.35 10.77,76.35 10.58,76.17 10.58,75.9 10.77,75.72 12.08,75.72 12.27,75.53 12.27,75.27 12.08,75.08 10.77,75.08 10.58,74.9 10.58,74.63 10.77,74.45 12.08,74.45 12.27,74.26 12.27,74 12.08,73.81 10.77,73.81 10.58,73.63 10.58,73.36 10.77,73.18 12.08,73.18 12.27,72.99 12.27,72.73 12.08,72.54 10.77,72.54 10.58,72.36 10.58,72.09 10.77,71.91 12.08,71.91 12.27,71.72 12.27,71.46 12.08,71.27 10.77,71.27 10.58,71.09 10.58,70.82 10.77,70.64 12.08,70.64 12.27,70.45 12.27,67.01 9.14,63.88 9.14,53.73 v1(10.06,52.81)
EXP_GPIO0_41: length 67.9
  TOP w0.127: U2.C6 v1(13.5,52.57)
  BOTTOM w0.127: J1.37 54.95,83.43 50.56,79.05 20.73,79.05 17.85,76.16 17.85,62.7 15.62,60.48 R19.2 14.77,60.01 14.77,57.59 13.5,56.32 v1(13.5,52.57)
GPIO0_43/I2C2_SCL: length 13.6
  TOP w0.127: U1.6 7.69,76.94 8.21,77.46 11.57,77.46 14.31,80.2 J1.5
GPIO0_44/I2C2_SDA: length 11.2
  TOP w0.127: U1.5 8.19,76.37 8.36,76.54 v1(9.72,76.54)
  BOTTOM w0.127: J1.3 11.77,82.32 9.72,80.27 v1(9.72,76.54)
PR0_PRU0_GPO0: length 68.7
  TOP w0.127: U2.H4 11.1,47.77 10.14,47.77 v1(9.8,47.43)
  BOTTOM w0.127: R22.2 9.8,47.43 v1(9.8,47.43) 9.8,46.87 8.69,45.76 8.69,41.23 10.05,39.87 10.05,39.63 9.87,39.45 9.01,39.45 8.86,39.29 8.86,38.94 8.99,38.81 9.87,38.81 10.05,38.62 10.05,38.36 9.87,38.18 9,38.18 8.84,38.01 8.84,37.71 9,37.54 9.87,37.54 10.05,37.35 10.05,37.09 9.87,36.91 9.06,36.91 8.88,36.72 8.88,36.46 9.06,36.27 9.87,36.27 10.05,36.08 10.05,35.82 9.87,35.64 9.06,35.64 8.88,35.45 8.88,35.19 9.06,35 9.87,35 10.05,34.81 10.05,34.55 9.87,34.37 9.06,34.37 8.88,34.18 8.88,33.92 9.06,33.73 9.87,33.73 10.05,33.54 10.05,33.28 9.87,33.1 9.06,33.1 8.88,32.91 8.88,32.65 9.06,32.46 9.87,32.46 10.05,32.27 10.05,32.01 9.87,31.83 9.06,31.83 8.88,31.64 8.88,31.38 9.06,31.19 9.87,31.19 10.05,31 10.05,30.74 9.87,30.56 9.06,30.56 8.88,30.37 8.88,30.11 9.06,29.92 9.87,29.92 10.05,29.73 10.05,29.22 15.85,23.43 17.04,23.43 18.05,22.41 18.05,17.59 20.1,15.54 27.51,15.54 28.25,14.8 28.25,12.49 J3.13
PR0_PRU0_GPO1: length 68.6
  TOP w0.127: U2.J4 v1(11.1,46.97)
  BOTTOM w0.127: R21.2 11.59,46.97 v1(11.1,46.97) 11.1,46.38 11.7,45.78 11.7,44.63 12.08,44.24 12.08,30.68 13.38,29.38 13.84,29.38 15.4,30.94 15.66,30.94 15.85,30.75 15.85,30.49 14.34,28.98 14.34,28.71 14.52,28.53 14.78,28.53 16.3,30.04 16.52,30.04 16.75,29.81 16.75,29.59 15.23,28.08 15.23,27.82 15.42,27.63 15.68,27.63 17.17,29.12 17.44,29.12 17.64,28.92 17.64,28.69 16.13,27.18 16.13,26.92 16.32,26.73 16.58,26.73 18.08,28.23 18.32,28.23 18.55,28 18.55,27.81 17.03,26.28 17.03,26.02 17.22,25.83 17.48,25.83 18.88,27.23 19.21,27.23 19.35,27.1 19.35,26.8 17.93,25.38 17.93,25.02 20.75,22.2 20.75,17.81 21.72,16.85 28.14,16.85 29.55,15.44 J3.14
PR0_PRU0_GPO2: length 68
  TOP w0.127: U2.K4 11.5,44.92 10.78,44.2 9.66,44.2 9.06,43.6 R11.2 8.42,42.36 8.15,42.1 8.15,40.37 9.97,38.54 9.97,37.03 10.48,36.53 10.48,36.26 9.83,35.62 9.83,35.36 10.02,35.17 10.28,35.17 10.93,35.82 11.19,35.82 11.38,35.63 11.38,35.37 10.77,34.76 10.77,34.53 10.96,34.34 11.25,34.34 11.82,34.92 12.09,34.92 12.27,34.73 12.27,34.47 11.7,33.89 11.7,33.7 11.96,33.43 12.14,33.43 12.72,34.02 12.99,34.02 13.17,33.83 13.17,33.57 12.6,33 12.6,32.75 12.82,32.53 13.03,32.53 13.62,33.12 13.88,33.12 14.07,32.94 14.07,32.67 13.44,32.04 13.44,31.86 13.62,31.68 13.8,31.68 14.41,32.29 14.71,32.29 14.97,32.04 14.97,31.77 14.32,31.13 14.32,30.87 14.51,30.68 14.77,30.68 15.42,31.33 15.68,31.33 15.87,31.14 15.87,30.88 15.27,30.28 15.27,30.01 15.44,29.83 15.72,29.83 16.31,30.43 16.58,30.43 16.76,30.24 16.76,29.98 16.16,29.38 16.16,29.08 16.31,28.93 16.61,28.93 17.21,29.53 17.5,29.53 23.18,23.85 23.18,13.07 23.94,12.31 30.96,12.31 J3.15
PR0_PRU0_GPO3: length 67.8
  TOP w0.127: J3.16 30.85,14.96 28.2,14.96 25.79,17.36 25.79,24.78 25.04,25.53 24.74,25.53 24.2,24.99 23.9,24.99 23.75,25.14 23.75,25.44 24.29,25.98 24.29,26.24 24.1,26.43 23.84,26.43 23.3,25.89 22.98,25.89 22.85,26.02 22.85,26.34 23.39,26.88 23.39,27.14 23.21,27.33 22.94,27.33 22.4,26.79 22.08,26.79 21.95,26.91 21.95,27.24 22.49,27.78 22.49,28.04 22.31,28.23 22.04,28.23 21.5,27.68 21.18,27.68 21.05,27.81 21.05,28.13 21.6,28.67 21.6,28.94 21.41,29.12 21.15,29.12 20.61,28.58 20.28,28.58 20.16,28.71 20.16,29.03 20.7,29.57 20.7,29.84 20.51,30.02 20.25,30.02 19.71,29.48 19.44,29.48 19.26,29.67 19.26,29.93 19.8,30.47 19.8,30.73 19.61,30.92 19.35,30.92 18.81,30.38 18.55,30.38 18.36,30.56 18.36,30.83 18.9,31.37 18.9,31.63 18.72,31.82 18.45,31.82 17.91,31.28 17.65,31.28 17.46,31.46 17.46,31.73 18,32.27 18,32.53 17.82,32.72 17.55,32.72 17.01,32.17 16.75,32.17 16.56,32.36 16.56,32.62 17.11,33.16 17.11,33.43 16.92,33.61 16.66,33.61 16.12,33.07 15.85,33.07 15.67,33.26 15.67,33.52 16.21,34.06 16.21,34.33 16.02,34.51 15.76,34.51 15.22,33.97 14.95,33.97 14.77,34.16 14.77,34.42 15.31,34.96 15.31,35.22 15.12,35.41 14.86,35.41 14.32,34.87 14.06,34.87 13.87,35.05 13.87,35.32 14.41,35.86 14.41,36.12 14.23,36.31 13.96,36.31 13.42,35.77 13.16,35.77 12.97,35.95 12.97,36.22 13.51,36.76 13.51,37.02 12.26,38.27 12.26,42.01 11.91,42.36 R12.2 11.32,43.38 12.3,44.36 U2.K5
PR0_PRU0_GPO4: length 68
  TOP w0.127: J3.17 33.3,12.51 33.3,14.85 32.13,16.02 30.11,16.02 28.2,17.93 28.2,26.58 22.4,32.39 22.14,32.39 21.27,31.52 21.01,31.52 20.82,31.71 20.82,31.97 21.69,32.84 21.69,33.1 21.5,33.29 21.24,33.29 20.37,32.42 20.11,32.42 19.92,32.61 19.92,32.87 20.79,33.74 20.79,34 20.6,34.19 20.34,34.19 19.47,33.32 19.21,33.32 19.02,33.51 19.02,33.77 19.89,34.63 19.89,34.9 19.7,35.08 19.44,35.08 18.58,34.22 18.31,34.22 18.13,34.4 18.13,34.67 18.99,35.53 18.99,35.8 18.81,35.98 18.54,35.98 17.68,35.12 17.41,35.12 17.23,35.3 17.23,35.56 18.09,36.43 18.09,36.69 17.91,36.88 17.65,36.88 16.78,36.01 16.52,36.01 16.33,36.2 16.33,36.46 17.2,37.33 17.2,37.59 17.01,37.78 16.75,37.78 15.88,36.91 15.62,36.91 15.43,37.1 15.43,37.36 16.3,38.23 16.3,38.49 16.11,38.68 15.85,38.68 14.98,37.81 14.72,37.81 14.53,38 14.53,38.26 14.82,38.54 14.82,38.72 12.85,40.7 12.85,42.14 13.07,42.36 R13.2 13.58,43.84 13.1,44.32 U2.K6
PR0_PRU0_GPO5: length 67.9
  TOP w0.127: U2.J7 v1(14.3,46.97)
  BOTTOM w0.127: J3.18 35.98,15.08 35.98,26.45 25.13,37.3 25.13,37.82 26.22,38.91 26.22,39.17 26.04,39.35 25.76,39.35 24.55,38.14 24.29,38.14 24.1,38.33 24.1,38.59 25.31,39.8 25.31,40.05 25.1,40.26 24.88,40.26 23.65,39.04 23.39,39.04 23.2,39.22 23.2,39.49 24.46,40.75 24.46,41.07 24.34,41.2 24.01,41.2 22.75,39.94 22.49,39.94 22.3,40.12 22.3,40.39 23.54,41.63 23.54,41.83 23.32,42.06 23.08,42.06 21.86,40.84 21.59,40.84 21.41,41.02 21.41,41.28 22.65,42.53 22.65,42.74 22.42,42.97 22.2,42.97 20.96,41.73 20.69,41.73 20.51,41.92 20.51,42.18 21.75,43.43 21.75,43.64 21.53,43.86 21.29,43.86 20.06,42.63 18.66,42.63 15.89,45.4 15.89,46.44 15.49,46.85 R23.2 14.68,47.35 v1(14.3,46.97)
PR0_PRU0_GPO6: length 68
  TOP w0.127: U2.K7 13.9,44.77 15.84,42.83 R14.2 16.42,42.36 18.6,40.19 18.6,39.92 17.61,38.93 17.61,38.67 17.8,38.48 18.06,38.48 19.05,39.47 19.31,39.47 19.5,39.29 19.5,39.03 18.51,38.04 18.51,37.77 18.69,37.59 18.96,37.59 19.95,38.58 20.21,38.58 20.4,38.39 20.4,38.13 19.41,37.14 19.41,36.87 19.59,36.69 19.85,36.69 20.84,37.68 21.11,37.68 21.29,37.49 21.29,37.23 20.3,36.24 20.3,35.98 20.49,35.79 20.75,35.79 21.74,36.78 22.01,36.78 22.19,36.59 22.19,36.33 21.2,35.34 21.2,35.08 21.39,34.89 21.65,34.89 22.64,35.88 22.9,35.88 23.09,35.7 23.09,35.43 22.1,34.44 22.1,34.18 22.29,33.99 22.55,33.99 23.54,34.98 23.8,34.98 23.99,34.8 23.99,34.54 23.03,33.58 23.03,33.28 23.18,33.13 23.48,33.13 24.44,34.09 24.76,34.09 30.9,27.95 30.9,17.91 31.64,17.16 33.16,17.16 35.85,14.47 35.85,12.5 J3.19
PR0_PRU0_GPO7: length 67.9
  TOP w0.127: U2.J8 16.24,47.37 18.35,45.27 R10.2 17.72,43.29 17.54,43.11 17.54,42.1 18.31,41.33 19.96,41.33 21.1,40.19 22.24,40.19 22.45,39.99 22.45,39.68 21.68,38.91 21.68,38.65 21.86,38.46 22.13,38.46 22.84,39.17 23.1,39.17 23.29,38.99 23.29,38.72 22.58,38.01 22.58,37.75 22.76,37.56 23.03,37.56 23.73,38.27 24,38.27 24.18,38.09 24.18,37.82 23.47,37.11 23.47,36.85 23.66,36.67 23.92,36.67 24.63,37.38 24.9,37.38 25.08,37.19 25.08,36.93 24.37,36.22 24.37,35.95 24.56,35.77 24.82,35.77 25.53,36.48 25.79,36.48 25.98,36.29 25.98,36.03 25.27,35.32 25.27,35.06 25.46,34.87 25.72,34.87 26.43,35.58 26.69,35.58 26.88,35.39 26.88,35.13 26.17,34.42 26.17,34.16 26.35,33.97 26.62,33.97 27.33,34.68 27.59,34.68 27.78,34.5 27.78,34.23 27.07,33.52 27.07,33.26 27.25,33.07 27.52,33.07 28.22,33.78 28.49,33.78 28.67,33.6 28.67,33.33 27.96,32.62 27.96,32.42 28.21,32.18 28.41,32.18 29.12,32.88 29.39,32.88 29.57,32.7 29.57,32.44 28.86,31.73 28.86,31.46 29.05,31.28 29.31,31.28 30.02,31.99 30.28,31.99 33.26,29.01 33.26,18.07 34.34,16.98 35.26,16.98 37.17,15.08 J3.20
PR0_PRU0_GPO11: length 68
  TOP w0.127: U2.D5 v1(11.9,51.77) ; v1(7.03,47.93) 6.43,47.93 5.48,46.98 5.48,37.38 5.98,36.88 5.98,36.61 5.17,35.81 5.17,35.54 5.36,35.36 5.62,35.36 6.43,36.17 6.69,36.17 6.88,35.98 6.88,35.72 6.07,34.91 6.07,34.64 6.25,34.46 6.52,34.46 7.33,35.27 7.59,35.27 7.78,35.08 7.78,34.82 6.97,34.01 6.97,33.75 7.15,33.56 7.42,33.56 8.22,34.37 8.49,34.37 8.67,34.18 8.67,33.92 7.86,33.11 7.86,32.85 8.05,32.66 8.31,32.66 9.12,33.47 9.39,33.47 9.57,33.29 9.57,33.02 8.76,32.21 8.76,31.95 8.95,31.76 9.21,31.76 10.02,32.57 10.28,32.57 10.47,32.39 10.47,32.12 9.66,31.32 9.66,31.05 9.85,30.87 10.11,30.87 10.92,31.68 11.18,31.68 20.64,22.21 20.64,12.47 J3.7
  BOTTOM w0.127: v1(7.03,47.93) 7.03,47.93 7.03,48.72 R20.2 7.04,49.33 7.6,49.89 10.01,49.89 v1(11.9,51.77)
PR0_PRU0_GPO12: length 68
  TOP w0.127: J3.9 26.01,9.64 38.58,9.64 39.26,10.32 39.26,14.36 35.92,17.71 35.92,30.1 20.08,45.93 20.08,46.66 18.95,47.79 R9.2 18.44,48.43 U2.C8
PR0_PRU0_GPO14: length 67.9
  TOP w0.127: U2.C7 v1(14.3,52.57)
  BOTTOM w0.127: v1(14.3,52.57) 21.09,45.78 25.88,45.78 38.5,33.16 38.5,10.47 37.73,9.7 28.49,9.7 J3.11
PRU_DETECT: length 1.5
  TOP w0.127: R16.2 J3.3
RPI_HAT_DETECT: length 2.5
  BOTTOM w0.127: J1.39 R17.2
N19755073: length 1.8
  TOP w0.127: R15.2 LD1.2

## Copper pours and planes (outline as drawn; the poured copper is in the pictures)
DGND on TOP: 1.02,8.73 1.02,90.03 62.27,90.03 62.27,76.52 20.28,76.52 20.28,47.62 55.45,47.62 55.45,8.73 ; 16 cut-outs
DGND on BOTTOM: 1.02,8.73 1.02,90.03 62.27,90.03 62.27,76.52 20.28,76.52 20.28,47.62 55.45,47.62 55.45,8.73 ; 7 cut-outs
DGND on L02_GND01, L03_PWR01: 1.02,8.73 1.02,90.03 62.27,90.03 62.27,76.52 20.28,76.52 20.28,47.62 55.45,47.62 55.45,8.73
VCC_3V3_NAND on L03_PWR01: 13.19,89.98 1.02,89.98 1.02,8.73 15.13,8.73 15.13,16.23 4.46,16.23 4.46,47.56 5.48,48.57 8.02,48.57 8.4,48.19 11.81,48.19 13.19,49.57

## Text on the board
Ref Des/Assembly Bottom: PROC143E1 BOTTOM ASSEMBLY REV.A
User.Comments: CR_PHY_2 | CR_PPP_17 | CR_R_4 | CR_PLL_2 | CR_1_6 | CR_R_2 | CR_PLL_1 | CR_R_1 | CR_JTAG_1 | CR_UNNAMED_1 | CR_UNNAMED_2 | CR_222_1 | CR_222_2 | CR_JTAG_2 | A
Ref Des/Assembly Top: PROC143E1 TOP ASSEMBLY REV.A
Ref Des/Silkscreen Top: x8 NAND CARD | PROC143E1
User.6: 2 | 60 | 59 | 10 | 9 | R | VAGG - BACKPLANE  CARD | FY20-21/00636000401 | Rev. A | SL# | Design by Indians | MADE IN INDIA | BOTTOM ASSEMBLY OF VAGG BACKPLANE  BOARD REV. A | SHEET    OF 23 | DOMLUR EXTENSION, BANGALORE-560 071 | #60, ADARSH REGENT, 100'FT RING ROAD, | MS_NPOL_BACKPLANE_CARD | TITLE: | SCALE: 1 | A | REV | 10FEB22 | DATE: | MISTRAL | MISTRAL SOLUTIONS PVT.LTD.,
User.9: A12 | 2 | 19 | 16 | 4 | 3 | 6 | 48 | 33 | 8 | 5 | 9 | 40 | 39 | 32 | 25 | 1 | A | B | C | D | 64 | 17 | 49 | 96 | 65 | 75 | 23 | 74 | 22 | 37 | 54 | 18 | 20 | 97 | 128 | B1 | B12 | 10 | 36 | 55 | 72 | 24 | 7 | 15 | 12 | 14 | 28 | 27 | 11 | OPN# | SL# | ASSY# | DISPLAY | BOARD NAME: | AM62x EVM  BOARD | REV: A | DATE: 23/08/21 | DESCRIPTION: | SHEET | OF | PROC114E1 | SCALE: 1 | PROC101A | AM64x/AM243x EVM | TEXAS INSTRUMENTS | PROC114E1 ASSEMBLY TOP REV A
User.10: R | TITLE: | x8 NAND CARD | #60, ADARSH REGENT, 100'FT RING ROAD, | DOMLUR EXTENSION, BANGALORE-560 071 | PRIMARY-SIDE-SIG | SHEET    OF 11 | DATE: | 07MAR22 | REV | A | 04 | SCALE: 1 | MISTRAL | MISTRAL SOLUTIONS PVT.LTD.,
User.11: R | TITLE: | x8 NAND CARD | #60, ADARSH REGENT, 100'FT RING ROAD, | DOMLUR EXTENSION, BANGALORE-560 071 | PRIMARY-SIDE-SIG | SHEET    OF 11 | DATE: | 07MAR22 | REV | A | 04 | SCALE: 1 | MISTRAL | MISTRAL SOLUTIONS PVT.LTD.,
User.12: RC
User.39: MICROSTRIP | L1 | L4 | 5.0 | NA | 50 | L2 | L3
User.41: REV # | SCALE:NONE | SIZE | DESCRIPTION | FILE NAME: | REVISIONS | CCN # | DRAWING NO. | DDMMYY | DATE | OF | REV | SHEET | 02 | D | FY200526000201 | A
User.43: 02
User.45: FIGURE | SIZE | 8.0 | 46.0 | 32.0 | 126.0 | DRILL CHART: TOP to BOTTOM | ALL UNITS ARE IN MILS | TOLERANCE | +3.0/-3.0 | PLATED | NON-PLATED | QTY | 414 | 88 | 120 | 4
